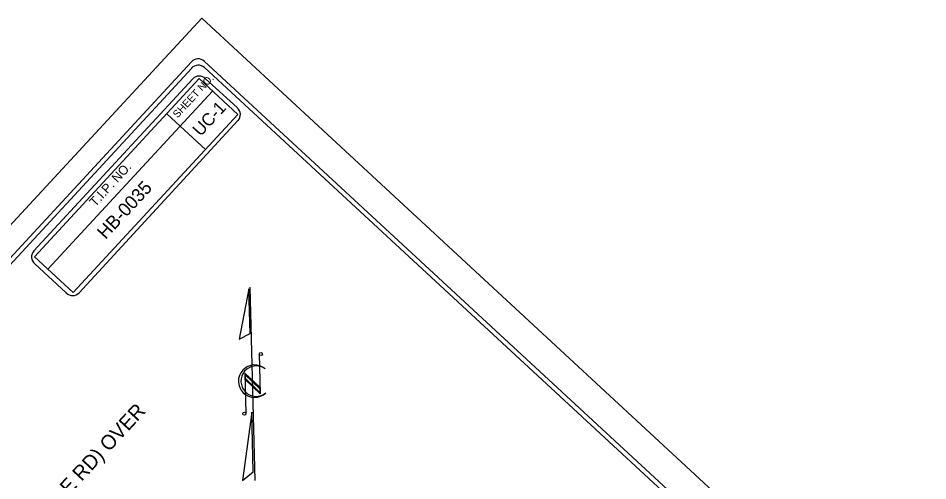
# Model space of a CAD drawing. Extents: x 1766669 to 1770980, y 998119 to 1002502.
# Drawn here: x 1768756 to 1770980, y 1001372 to 1002502 of the extents above; entities that cross this region are included whole.
import ezdxf

# ---------------------------------------------------------------- set-up
doc = ezdxf.new("R2010")
doc.units = 0
for name, color, linetype in [('Default Symbol CELL', 7, 'Continuous'), ('Exist Survey Observation Group', 7, 'Continuous'), ('PH Exist DTM Breakline', 7, 'Continuous')]:
    doc.layers.add(name, color=color, linetype=linetype)

msp = doc.modelspace()

# ---------------------------------------------------------------- linework, layer by layer
at = {"layer": 'Default Symbol CELL'}
for p, q in [((1769179.9, 1002395.5), (1766757.7, 999775.1)), ((1769180.5, 1002379.9), (1766847.8, 999856.4)), ((1769183.2, 1002354.1), (1768794.6, 1001933.3)), ((1768796.4, 1001919), (1769198.9, 1002354.3)), ((1769198.9, 1002354.3), (1769293.6, 1002266.6)), ((1769291.8, 1002283.4), (1769214.6, 1002354)), ((1768829, 1001888.6), (1769231.5, 1002323.8)), ((1768891.1, 1001831.3), (1769293.6, 1002266.6)), ((1769120.2, 1002267.7), (1769214.4, 1002180.7)), ((1768905.1, 1001830.9), (1769293.7, 1002251.7)), ((1768796.4, 1001919), (1768891.1, 1001831.3)), ((1768797, 1001901.6), (1768873.9, 1001830.5))]:
    msp.add_line(p, q, dxfattribs=at)
for points in [[(1770872.9, 1000860.4), (1769210.9, 1002396.7)], [(1770558.9, 1001135.7), (1769211.5, 1002381.2)]]:
    msp.add_lwpolyline(points, dxfattribs=at)
for centre in [(1769195.9, 1002380.6), (1769196.5, 1002365.1)]:
    msp.add_arc(centre, 22, 47.2512, 137.2512, dxfattribs=at)
for centre, major_axis, ratio, start_param, end_param in [((1769200.2, 1002338.4), (-16.9, 15.6), 0.926296, 4.712758, 6.283554), ((1769277.1, 1002267.3), (16.9, -15.6), 0.941469, 0.000472, 1.571267), ((1768811.5, 1001917.5), (-16.9, 15.6), 0.941469, 0.000468, 1.571265), ((1768888.5, 1001846.5), (16.9, -15.6), 0.941469, 4.712857, 6.283654)]:
    msp.add_ellipse(centre, major_axis=major_axis, ratio=ratio, start_param=start_param, end_param=end_param, dxfattribs=at)
at = {"layer": 'Exist Survey Observation Group'}
for p, q in [((1769335.4, 1001372.7), (1769323.6, 1001845.1)), ((1769345.5, 1001681.2), (1769347.9, 1001584.2)), ((1769359.8, 1001645.4), (1769360.3, 1001645)), ((1769347.6, 1001599.3), (1769310.5, 1001634.6)), ((1769310.5, 1001634.6), (1769313, 1001536)), ((1769347.7, 1001595.8), (1769310.6, 1001631)), ((1769310.6, 1001631), (1769310.9, 1001622.1)), ((1769347.9, 1001586.9), (1769310.9, 1001622.1)), ((1769310.9, 1001622.1), (1769347.9, 1001586.9)), ((1769347.9, 1001584.2), (1769310.9, 1001619.4)), ((1769347.9, 1001586.9), (1769347.7, 1001595.8))]:
    msp.add_line(p, q, dxfattribs=at)
for points in [[(1769320.4, 1001840.9), (1769296.5, 1001717.5), (1769323.2, 1001731.9)], [(1769327.4, 1001539), (1769304.8, 1001371.9), (1769331, 1001393.7)]]:
    msp.add_lwpolyline(points, close=True, dxfattribs=at)
for centre in [(1769349.4, 1001681.2), (1769309.2, 1001535.8)]:
    msp.add_circle(centre, 3.85, dxfattribs=at)
for centre, radius, start, end in [((1769334.4, 1001615), 39.7, 49.2729, 313.8269), ((1769338.2, 1001615.1), 37.2, 54.5279, 310.0616)]:
    msp.add_arc(centre, radius, start, end, dxfattribs=at)
at = {"layer": 'PH Exist DTM Breakline'}
msp.add_lwpolyline([(1766668.6, 999760.2), (1769205.6, 1002501.9), (1770979.8, 1000860.3), (1768442.7, 998118.5)], close=True, dxfattribs=at)

# ---------------------------------------------------------------- texts
at = {"layer": 'Default Symbol CELL'}
for s, height, rotation, p in [('SHEET NO.', 18.49, 47.2797, (1769145.9, 1002256.6)), ('UC-1', 30.51, 47.2797, (1769202.2, 1002211.4)), ('T.I.P. NO.', 22.37, 47.2797, (1768944.9, 1002039.9)), ('HB-0035', 32.42, 47.2797, (1768969.9, 1001959.9)), ('LOCATION: REPLACE BRIDGE #780177 ON SR 1535 (PRICE RD) OVER', 35.736, 47.237, (1767986.5, 1000368.3))]:
    msp.add_text(s, height=height, rotation=rotation, dxfattribs=at).set_placement(p)

doc.saveas('drawing.dxf')
